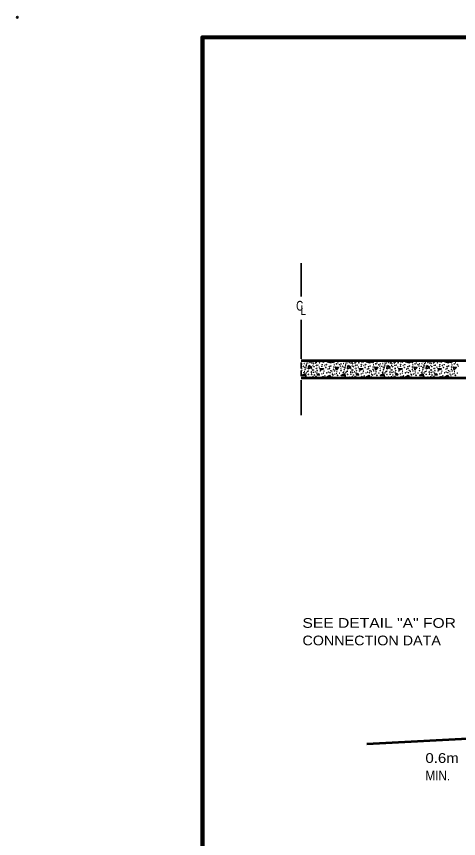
# Model space of a CAD drawing. Extents: x -89 to 766, y -60 to 484.
# Drawn here: x -89.2 to 47, y 231 to 484.5 of the extents above; entities that cross this region are included whole.
import ezdxf

# ---------------------------------------------------------------- set-up
doc = ezdxf.new("R2010")
doc.units = 0
doc.header["$LTSCALE"] = 1.1
doc.header["$PDMODE"] = 32
doc.header["$PDSIZE"] = 0.55
doc.layers.add('1', color=7, linetype='Continuous', lineweight=35)

msp = doc.modelspace()

# ---------------------------------------------------------------- linework, layer by layer
at = {"layer": '1'}
for p, q in [((-1.421, 398.17), (-1.421, 408.37)), ((-1.421, 378.97), (-1.421, 390.97)), ((-1.421, 377.77), (-1.421, 375.97)), ((-1.421, 375.37), (-1.421, 373.57)), ((-1.421, 372.37), (-1.421, 361.57))]:
    msp.add_line(p, q, dxfattribs=at)
at = {"layer": '1', "lineweight": 53}
for p, q in [((95.179, 372.97), (-1.421, 372.97)), ((65.554, 262.572), (18.818, 260.122))]:
    msp.add_line(p, q, dxfattribs=at)
at = {"layer": '1', "lineweight": 158}
msp.add_lwpolyline([(759.817, 478.083), (-31.883, 477.983), (-31.783, -48.017)], dxfattribs=at)
at = {"layer": '1', "lineweight": 53}
msp.add_lwpolyline([(-1.421, 378.37), (95.179, 378.37), (95.179, 375.966), (95.179, 372.97)], dxfattribs=at)
at = {"layer": '1'}
for points in [[(-1.143, 378.37), (-0.01, 378.239), (-0.038, 378.37)], [(10.953, 378.37), (12.086, 378.239), (12.058, 378.37)], [(23.049, 378.37), (24.182, 378.239), (24.154, 378.37)], [(35.145, 378.37), (36.278, 378.239), (36.25, 378.37)], [(0.926, 376.871), (1.766, 376.391), (0.734, 375.887), (0.878, 376.895)], [(9.446, 375.431), (9.158, 376.391), (10.094, 376.199), (9.422, 375.479)], [(13.022, 376.871), (13.862, 376.391), (12.83, 375.887), (12.974, 376.895)], [(21.542, 375.431), (21.254, 376.391), (22.19, 376.199), (21.518, 375.479)], [(25.118, 376.871), (25.958, 376.391), (24.926, 375.887), (25.07, 376.895)], [(33.638, 375.431), (33.35, 376.391), (34.286, 376.199), (33.614, 375.479)], [(37.214, 376.871), (38.054, 376.391), (37.022, 375.887), (37.166, 376.895)], [(45.734, 375.431), (45.446, 376.391), (46.382, 376.199), (45.71, 375.479)], [(-0.13, 374.279), (-1.258, 373.823), (-0.01, 373.679), (-0.13, 374.231)], [(3.902, 374.447), (3.446, 373.967), (4.142, 373.919), (3.902, 374.399)], [(7.382, 373.823), (6.59, 373.391), (7.766, 373.175), (7.334, 373.847)], [(11.966, 374.279), (10.838, 373.823), (12.086, 373.679), (11.966, 374.231)], [(15.998, 374.447), (15.542, 373.967), (16.238, 373.919), (15.998, 374.399)], [(19.478, 373.823), (18.686, 373.391), (19.862, 373.175), (19.43, 373.847)], [(24.062, 374.279), (22.934, 373.823), (24.182, 373.679), (24.062, 374.231)], [(28.094, 374.447), (27.638, 373.967), (28.334, 373.919), (28.094, 374.399)], [(31.574, 373.823), (30.782, 373.391), (31.958, 373.175), (31.526, 373.847)], [(36.158, 374.279), (35.03, 373.823), (36.278, 373.679), (36.158, 374.231)], [(40.19, 374.447), (39.734, 373.967), (40.43, 373.919), (40.19, 374.399)], [(43.67, 373.823), (42.878, 373.391), (44.054, 373.175), (43.622, 373.847)]]:
    msp.add_lwpolyline(points, dxfattribs=at)
for points in [[(7.358, 378.37), (6.59, 377.951), (7.766, 377.735)], [(19.454, 378.37), (18.686, 377.951), (19.862, 377.735)], [(31.55, 378.37), (30.782, 377.951), (31.958, 377.735)], [(43.646, 378.37), (42.878, 377.951), (44.054, 377.735)], [(4.238, 375.935), (5.486, 375.791), (4.67, 375.503)], [(16.334, 375.935), (17.582, 375.791), (16.766, 375.503)], [(28.43, 375.935), (29.678, 375.791), (28.862, 375.503)], [(40.526, 375.935), (41.774, 375.791), (40.958, 375.503)]]:
    msp.add_lwpolyline(points, close=True, dxfattribs=at)
for centre in [(0.024, 378.073), (0.644, 377.676), (1.28, 377.819), (1.821, 377.644), (2.203, 377.994), (3.03, 378.01), (3.046, 377.628), (3.309, 377.914), (4.248, 377.708), (5.106, 377.978), (5.52, 377.93), (5.902, 378.217), (8.192, 377.867), (8.653, 377.755), (9.893, 377.692), (12.12, 378.073), (12.74, 377.676), (13.376, 377.819), (13.917, 377.644), (14.299, 377.994), (15.126, 378.01), (15.142, 377.628), (15.405, 377.914), (16.344, 377.708), (17.202, 377.978), (17.616, 377.93), (17.998, 378.217), (20.288, 377.867), (20.749, 377.755), (21.989, 377.692), (24.216, 378.073), (24.836, 377.676), (25.472, 377.819), (26.013, 377.644), (26.395, 377.994), (27.222, 378.01), (27.238, 377.628), (27.501, 377.914), (28.44, 377.708), (29.298, 377.978), (29.712, 377.93), (30.094, 378.217), (32.384, 377.867), (32.845, 377.755), (34.085, 377.692), (36.312, 378.073), (36.932, 377.676), (37.568, 377.819), (38.109, 377.644), (38.491, 377.994), (39.318, 378.01), (39.334, 377.628), (39.597, 377.914), (40.536, 377.708), (41.394, 377.978), (41.808, 377.93), (42.19, 378.217), (44.48, 377.867), (44.941, 377.755), (46.181, 377.692), (-1.28, 375.274), (-1.232, 377.374), (-1.201, 375.926), (-0.771, 376.626), (-0.453, 377.485), (-0.262, 376.228), (-0.246, 375.608), (0.088, 376.149), (0.103, 376.721), (0.183, 377.087), (0.31, 377.469), (0.819, 375.114), (1.71, 375.974), (2.107, 375.496), (2.266, 376.849), (2.33, 377.517), (2.378, 375.496), (2.537, 376.498), (3.213, 375.939), (3.237, 376.912), (3.484, 375.958), (3.484, 375.242), (3.739, 376.976), (4.136, 376.355), (4.454, 375.194), (4.947, 376.626), (5.011, 377.103), (5.647, 375.099), (5.838, 376.849), (6.172, 376.228), (6.315, 377.103), (6.888, 375.735), (7.222, 376.498), (7.269, 375.91), (7.683, 375.258), (7.715, 376.705), (8.112, 375.019), (8.589, 375.703), (8.637, 376.419), (8.796, 377.071), (8.812, 375.194), (9.448, 377.358), (9.591, 375.019), (10.371, 377.103), (10.705, 376.658), (10.816, 375.274), (10.864, 377.374), (10.895, 375.926), (11.325, 376.626), (11.643, 377.485), (11.834, 376.228), (11.85, 375.608), (12.184, 376.149), (12.199, 376.721), (12.279, 377.087), (12.406, 377.469), (12.915, 375.114), (13.806, 375.974), (14.203, 375.496), (14.362, 376.849), (14.426, 377.517), (14.474, 375.496), (14.633, 376.498), (15.309, 375.939), (15.333, 376.912), (15.58, 375.958), (15.58, 375.242), (15.835, 376.976), (16.232, 376.355), (16.55, 375.194), (17.043, 376.626), (17.107, 377.103), (17.743, 375.099), (17.934, 376.849), (18.268, 376.228), (18.411, 377.103), (18.984, 375.735), (19.318, 376.498), (19.365, 375.91), (19.779, 375.258), (19.811, 376.705), (20.208, 375.019), (20.685, 375.703), (20.733, 376.419), (20.892, 377.071), (20.908, 375.194), (21.544, 377.358), (21.687, 375.019), (22.467, 377.103), (22.801, 376.658), (22.912, 375.274), (22.96, 377.374), (22.991, 375.926), (23.421, 376.626), (23.739, 377.485), (23.93, 376.228), (23.946, 375.608), (24.28, 376.149), (24.295, 376.721), (24.375, 377.087), (24.502, 377.469), (25.011, 375.114), (25.902, 375.974), (26.299, 375.496), (26.458, 376.849), (26.522, 377.517), (26.57, 375.496), (26.729, 376.498), (27.405, 375.939), (27.429, 376.912), (27.676, 375.958), (27.676, 375.242), (27.931, 376.976), (28.328, 376.355), (28.646, 375.194), (29.139, 376.626), (29.203, 377.103), (29.839, 375.099), (30.03, 376.849), (30.364, 376.228), (30.507, 377.103), (31.08, 375.735), (31.414, 376.498), (31.461, 375.91), (31.875, 375.258), (31.907, 376.705), (32.304, 375.019), (32.781, 375.703), (32.829, 376.419), (32.988, 377.071), (33.004, 375.194), (33.64, 377.358), (33.783, 375.019), (34.563, 377.103), (34.897, 376.658), (35.008, 375.274), (35.056, 377.374), (35.087, 375.926), (35.517, 376.626), (35.835, 377.485), (36.026, 376.228), (36.042, 375.608), (36.376, 376.149), (36.391, 376.721), (36.471, 377.087), (36.598, 377.469), (37.107, 375.114), (37.998, 375.974), (38.395, 375.496), (38.554, 376.849), (38.618, 377.517), (38.666, 375.496), (38.825, 376.498), (39.501, 375.939), (39.525, 376.912), (39.772, 375.958), (39.772, 375.242), (40.027, 376.976), (40.424, 376.355), (40.742, 375.194), (41.235, 376.626), (41.299, 377.103), (41.935, 375.099), (42.126, 376.849), (42.46, 376.228), (42.603, 377.103), (43.176, 375.735), (43.51, 376.498), (43.557, 375.91), (43.971, 375.258), (44.003, 376.705), (44.4, 375.019), (44.877, 375.703), (44.925, 376.419), (45.084, 377.071), (45.1, 375.194), (45.736, 377.358), (45.879, 375.019), (46.659, 377.103), (46.993, 376.658), (-0.612, 374.627), (-0.358, 375.003), (0.024, 373.513), (0.151, 374.579), (0.485, 374.971), (0.644, 373.116), (0.787, 374.134), (1.28, 373.259), (1.742, 374.691), (1.758, 374.892), (1.789, 374.15), (1.821, 373.084), (2.203, 373.434), (2.346, 374.754), (2.6, 373.927), (2.934, 374.908), (3.03, 373.45), (3.046, 373.068), (3.309, 373.354), (3.373, 374.532), (4.248, 373.148), (4.979, 374.277), (5.106, 373.418), (5.52, 374.484), (5.52, 373.37), (5.902, 373.657), (6.49, 374.595), (6.967, 374.828), (7.444, 374.675), (8.192, 374.198), (8.192, 373.307), (8.383, 373.943), (8.653, 373.195), (9.003, 374.198), (9.48, 374.389), (9.75, 373.832), (9.814, 373.832), (9.893, 373.132), (10.418, 374.516), (11.484, 374.627), (11.738, 375.003), (12.12, 373.513), (12.247, 374.579), (12.581, 374.971), (12.74, 373.116), (12.883, 374.134), (13.376, 373.259), (13.838, 374.691), (13.854, 374.892), (13.885, 374.15), (13.917, 373.084), (14.299, 373.434), (14.442, 374.754), (14.696, 373.927), (15.03, 374.908), (15.126, 373.45), (15.142, 373.068), (15.405, 373.354), (15.469, 374.532), (16.344, 373.148), (17.075, 374.277), (17.202, 373.418), (17.616, 374.484), (17.616, 373.37), (17.998, 373.657), (18.586, 374.595), (19.063, 374.828), (19.54, 374.675), (20.288, 374.198), (20.288, 373.307), (20.479, 373.943), (20.749, 373.195), (21.099, 374.198), (21.576, 374.389), (21.846, 373.832), (21.91, 373.832), (21.989, 373.132), (22.514, 374.516), (23.58, 374.627), (23.834, 375.003), (24.216, 373.513), (24.343, 374.579), (24.677, 374.971), (24.836, 373.116), (24.979, 374.134), (25.472, 373.259), (25.934, 374.691), (25.95, 374.892), (25.981, 374.15), (26.013, 373.084), (26.395, 373.434), (26.538, 374.754), (26.792, 373.927), (27.126, 374.908), (27.222, 373.45), (27.238, 373.068), (27.501, 373.354), (27.565, 374.532), (28.44, 373.148), (29.171, 374.277), (29.298, 373.418), (29.712, 374.484), (29.712, 373.37), (30.094, 373.657), (30.682, 374.595), (31.159, 374.828), (31.636, 374.675), (32.384, 374.198), (32.384, 373.307), (32.575, 373.943), (32.845, 373.195), (33.195, 374.198), (33.672, 374.389), (33.942, 373.832), (34.006, 373.832), (34.085, 373.132), (34.61, 374.516), (35.676, 374.627), (35.93, 375.003), (36.312, 373.513), (36.439, 374.579), (36.773, 374.971), (36.932, 373.116), (37.075, 374.134), (37.568, 373.259), (38.03, 374.691), (38.046, 374.892), (38.077, 374.15), (38.109, 373.084), (38.491, 373.434), (38.634, 374.754), (38.888, 373.927), (39.222, 374.908), (39.318, 373.45), (39.334, 373.068), (39.597, 373.354), (39.661, 374.532), (40.536, 373.148), (41.267, 374.277), (41.394, 373.418), (41.808, 374.484), (41.808, 373.37), (42.19, 373.657), (42.778, 374.595), (43.255, 374.828), (43.732, 374.675), (44.48, 374.198), (44.48, 373.307), (44.671, 373.943), (44.941, 373.195), (45.291, 374.198), (45.768, 374.389), (46.038, 373.832), (46.102, 373.832), (46.181, 373.132), (46.706, 374.516)]:
    msp.add_circle(centre, 0.0318, dxfattribs=at)
for centre, start, end in [((9.75, 378.392), 223.38683, 316.61317), ((9.814, 378.392), 223.38683, 316.61317), ((21.846, 378.392), 223.38683, 316.61317), ((21.91, 378.392), 223.38683, 316.61317), ((33.942, 378.392), 223.38683, 316.61317), ((34.006, 378.392), 223.38683, 316.61317), ((46.038, 378.392), 223.38683, 316.61317), ((46.102, 378.392), 223.38683, 316.61317), ((-1.391, 376.658), 201.63508, 158.36492), ((2.33, 372.957), 24.63166, 155.36834), ((14.426, 372.957), 24.63166, 155.36834), ((26.522, 372.957), 24.63166, 155.36834), ((38.618, 372.957), 24.63166, 155.36834)]:
    msp.add_arc(centre, 0.0318, start, end, dxfattribs=at)
msp.add_point((-88.883, 484.183), dxfattribs=at)

# ---------------------------------------------------------------- texts
for s, width, p in [('C', 0.75, (-2.984, 393.781)), ('L', 0.75, (-1.627, 392.423)), ('SEE DETAIL "A" FOR', 1.2, (-1.046, 296.01)), ('CONNECTION DATA', 1.1, (-1.046, 290.61)), ('0.6m', 1.15, (36.846, 254.37)), ('MIN.', 0.9, (36.846, 248.97))]:
    msp.add_text(s, height=3, dxfattribs=dict(at, width=width)).set_placement(p)

doc.saveas('drawing.dxf')
